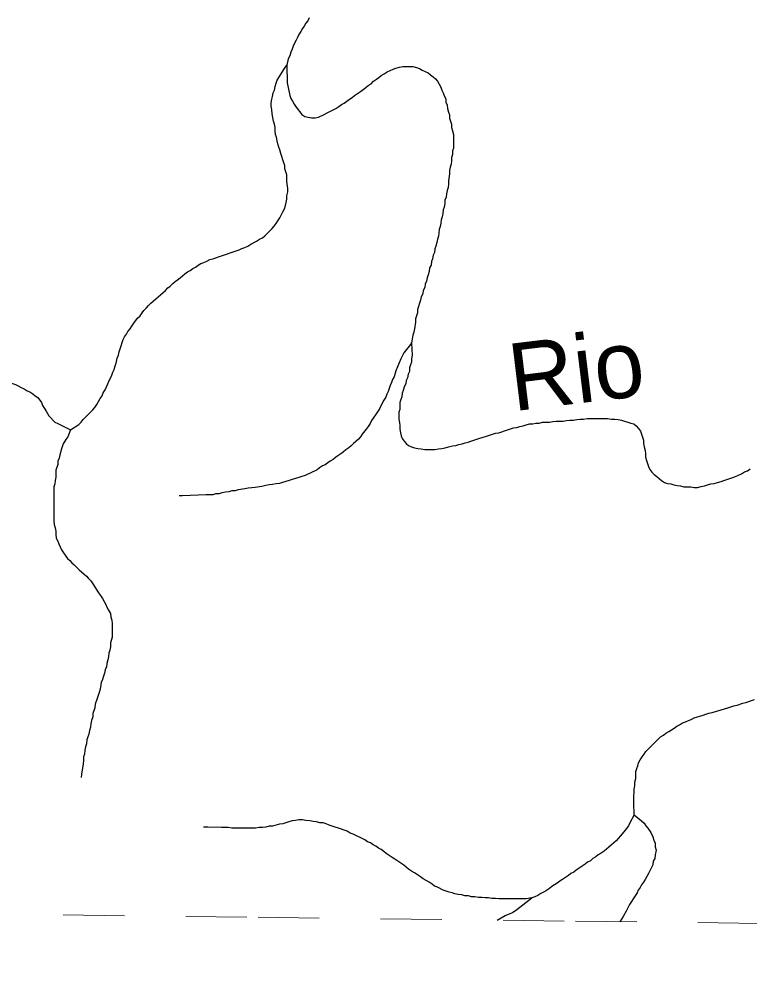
# Model space of a CAD drawing. Extents: x 652.3 to 678, y 7316.9 to 7344.9.
# Drawn here: x 670.031 to 671.224, y 7316.944 to 7318.499 of the extents above; entities that cross this region are included whole.
import ezdxf
from ezdxf.enums import TextEntityAlignment as Align

# ---------------------------------------------------------------- set-up
doc = ezdxf.new("R2010")
doc.units = 0
doc.header["$LTSCALE"] = 0.032
doc.linetypes.add('SHORT_DASHED', pattern=[2.7, 1.5, -1.2])
doc.layers.add('53', color=7, linetype='SHORT_DASHED', lineweight=13)
doc.layers.add('7', color=7, linetype='Continuous', lineweight=25)
doc.layers.add('61', color=7, linetype='Continuous')

msp = doc.modelspace()

# ---------------------------------------------------------------- linework, layer by layer
at = {"layer": '53'}
msp.add_lwpolyline([(666.2765, 7317.0825), (666.7945, 7317.0764), (667.3126, 7317.0703), (667.8307, 7317.0642), (668.3488, 7317.058), (668.8669, 7317.0519), (669.385, 7317.0457), (669.9031, 7317.0395), (670.4212, 7317.0333), (670.9393, 7317.027), (671.4574, 7317.0207), (671.9755, 7317.0145), (672.4936, 7317.0082), (673.0117, 7317.0018), (673.5298, 7316.9955), (674.0479, 7316.9891), (674.566, 7316.9828), (675.0841, 7316.9764), (675.6022, 7316.9699), (676.1203, 7316.9635), (676.6384, 7316.9571), (677.1565, 7316.9506), (677.6746, 7316.9441)], dxfattribs=at)
at = {"layer": '7'}
msp.add_line((670.4681, 7318.424), (670.4689, 7318.3954), dxfattribs=at)
for points in [[(670.5047, 7318.5012), (670.5023, 7318.4964), (670.4991, 7318.4925), (670.4967, 7318.4877), (670.4935, 7318.4837), (670.4911, 7318.4789), (670.488, 7318.4742), (670.4856, 7318.4694), (670.4832, 7318.4646), (670.4808, 7318.4598), (670.4784, 7318.4551), (670.4768, 7318.4503), (670.4744, 7318.4455), (670.4728, 7318.4392), (670.4704, 7318.4344), (670.4681, 7318.424)], [(670.4553, 7318.2904), (670.4537, 7318.2959), (670.4521, 7318.3007), (670.4514, 7318.3063), (670.4498, 7318.311), (670.449, 7318.3166), (670.449, 7318.3222), (670.4482, 7318.3278), (670.4466, 7318.3325), (670.4442, 7318.3445), (670.4434, 7318.3516), (670.4426, 7318.3572), (670.4426, 7318.3628), (670.4434, 7318.3683), (670.445, 7318.3731), (670.4458, 7318.3787), (670.4482, 7318.3835), (670.449, 7318.389), (670.4506, 7318.3946), (670.4521, 7318.3994), (670.4553, 7318.4041), (670.4641, 7318.4186), (670.4681, 7318.424)], [(670.4689, 7318.3954), (670.4728, 7318.3747), (670.4744, 7318.3699), (670.4776, 7318.3652), (670.48, 7318.3604), (670.4832, 7318.3556), (670.4927, 7318.3437), (670.4975, 7318.3405), (670.5031, 7318.3389), (670.5086, 7318.3381), (670.5142, 7318.3381), (670.5198, 7318.3389), (670.5293, 7318.3437), (670.5341, 7318.3461), (670.5484, 7318.3532), (670.5532, 7318.3564), (670.5572, 7318.3596), (670.562, 7318.362), (670.5659, 7318.3652), (670.5707, 7318.3683), (670.5747, 7318.3715), (670.5787, 7318.3747), (670.5834, 7318.3779), (670.5882, 7318.3811), (670.593, 7318.3843), (670.597, 7318.3874), (670.6009, 7318.3906), (670.6057, 7318.3938), (670.6097, 7318.3978), (670.6145, 7318.401), (670.6184, 7318.4041), (670.6224, 7318.4073), (670.6272, 7318.4097), (670.632, 7318.4129), (670.6415, 7318.4177), (670.6463, 7318.4193), (670.6519, 7318.4209), (670.6574, 7318.4216), (670.6741, 7318.4216), (670.6797, 7318.4201), (670.6845, 7318.4185), (670.6893, 7318.4161), (670.694, 7318.4137), (670.6988, 7318.4113), (670.7028, 7318.4081), (670.7068, 7318.4049), (670.7107, 7318.4018), (670.7139, 7318.3978), (670.7171, 7318.393), (670.7195, 7318.3882), (670.7211, 7318.3835), (670.7235, 7318.3787), (670.7251, 7318.3739), (670.7275, 7318.3691), (670.7275, 7318.3636), (670.7298, 7318.3588), (670.7306, 7318.3532), (670.7322, 7318.3476), (670.7338, 7318.3429), (670.7338, 7318.3373), (670.737, 7318.3278), (670.737, 7318.3222), (670.7386, 7318.3166), (670.7402, 7318.311), (670.7402, 7318.2888), (670.7386, 7318.284), (670.7386, 7318.2784), (670.737, 7318.2736), (670.737, 7318.2681), (670.7362, 7318.2625), (670.7346, 7318.2577), (670.7338, 7318.2522), (670.7338, 7318.2466), (670.7322, 7318.2355), (670.7322, 7318.2299), (670.7314, 7318.2243), (670.7298, 7318.2195), (670.729, 7318.214), (670.7283, 7318.2084), (670.7259, 7318.2036), (670.7259, 7318.1981), (670.7251, 7318.1925), (670.7235, 7318.1877), (670.7227, 7318.1821), (670.7219, 7318.1766), (670.7203, 7318.1718), (670.7195, 7318.1662), (670.7187, 7318.1607), (670.7171, 7318.1559), (670.7163, 7318.1503), (670.7155, 7318.1447), (670.7139, 7318.14), (670.7131, 7318.1344), (670.7115, 7318.1288), (670.71, 7318.1241), (670.7092, 7318.1185), (670.7068, 7318.1137), (670.706, 7318.1081), (670.7044, 7318.1034), (670.7036, 7318.0978), (670.7012, 7318.093)], [(670.1148, 7317.8289), (670.1283, 7317.8376), (670.1323, 7317.8416), (670.1355, 7317.8456), (670.1394, 7317.8495), (670.1434, 7317.8535), (670.1514, 7317.8615), (670.1546, 7317.8655), (670.1577, 7317.8702), (670.1609, 7317.875), (670.1633, 7317.8798), (670.1665, 7317.8846), (670.1681, 7317.8893), (670.1713, 7317.8941), (670.176, 7317.9037), (670.1776, 7317.9084), (670.18, 7317.9132), (670.1824, 7317.918), (670.184, 7317.9228), (670.1864, 7317.9275), (670.188, 7317.9331), (670.1896, 7317.9379), (670.1912, 7317.9458), (670.1935, 7317.9506), (670.1943, 7317.9562), (670.1975, 7317.9657), (670.1991, 7317.9713), (670.2007, 7317.9761), (670.2031, 7317.9808), (670.2063, 7317.9848), (670.2087, 7317.9896), (670.2126, 7317.9936), (670.215, 7317.9983), (670.2182, 7318.0031), (670.2246, 7318.0111), (670.2286, 7318.0151), (670.2317, 7318.0198), (670.2349, 7318.0238), (670.2389, 7318.0278), (670.2421, 7318.0318), (670.2461, 7318.0357), (670.25, 7318.0389), (670.254, 7318.0429), (670.258, 7318.0461), (670.262, 7318.0493), (670.266, 7318.0532), (670.2699, 7318.0564), (670.2739, 7318.0604), (670.2779, 7318.0636), (670.2819, 7318.0676), (670.2858, 7318.0707), (670.2898, 7318.0739), (670.2938, 7318.0771), (670.2978, 7318.0803), (670.3018, 7318.0835), (670.3057, 7318.0867), (670.3105, 7318.0891), (670.3145, 7318.0922), (670.3193, 7318.0946), (670.3232, 7318.0978), (670.328, 7318.1002), (670.3328, 7318.1018), (670.3376, 7318.1042), (670.3423, 7318.1066), (670.3471, 7318.1081), (670.3614, 7318.1129), (670.3662, 7318.1145), (670.3805, 7318.1193), (670.3853, 7318.1209), (670.3901, 7318.1225), (670.3949, 7318.1249), (670.3996, 7318.1264), (670.4044, 7318.1288), (670.4092, 7318.132), (670.4187, 7318.1368), (670.4235, 7318.14), (670.4283, 7318.1424), (670.4323, 7318.1455), (670.4442, 7318.1575), (670.4474, 7318.1615), (670.4506, 7318.1654), (670.4537, 7318.1702), (670.4569, 7318.175), (670.4617, 7318.1845), (670.4641, 7318.1893), (670.4657, 7318.1949), (670.4673, 7318.1997), (670.4681, 7318.2052), (670.4681, 7318.2108), (670.4697, 7318.2172), (670.4697, 7318.2227), (670.4681, 7318.2339), (670.4681, 7318.245), (670.4649, 7318.2546), (670.4649, 7318.2601), (670.4633, 7318.2649), (670.4617, 7318.2697), (670.4601, 7318.2752), (670.4585, 7318.28), (670.4569, 7318.2856), (670.4553, 7318.2904)], [(670.7012, 7318.093), (670.7004, 7318.0875), (670.6988, 7318.0819), (670.6972, 7318.0771), (670.6964, 7318.0715), (670.694, 7318.0668), (670.6932, 7318.0612), (670.6909, 7318.0564), (670.6901, 7318.0509), (670.6877, 7318.0461), (670.6861, 7318.0405), (670.6845, 7318.0357), (670.6829, 7318.0302), (670.6813, 7318.0254), (670.6813, 7318.0198), (670.6797, 7318.0151), (670.6781, 7318.0103), (670.6781, 7318.0047), (670.6765, 7317.9936), (670.6757, 7317.988), (670.6741, 7317.9832), (670.6718, 7317.9706)], [(670.6718, 7317.9706), (670.6698, 7317.9683), (670.659, 7317.9546), (670.6543, 7317.945), (670.6463, 7317.9251), (670.6431, 7317.9156), (670.6407, 7317.9108), (670.6391, 7317.906), (670.6367, 7317.9013), (670.6352, 7317.8965), (670.6336, 7317.8917), (670.6312, 7317.8869), (670.6296, 7317.8822), (670.6264, 7317.8774), (670.624, 7317.8726), (670.6192, 7317.8631), (670.6161, 7317.8583), (670.6129, 7317.8535), (670.6065, 7317.844), (670.6041, 7317.8392), (670.6009, 7317.8344), (670.5978, 7317.8297), (670.5914, 7317.8217), (670.5882, 7317.8177), (670.585, 7317.8137), (670.581, 7317.8098), (670.5771, 7317.8066), (670.5731, 7317.8026), (670.5691, 7317.7994), (670.5643, 7317.7962), (670.5604, 7317.7931), (670.5564, 7317.7899), (670.5516, 7317.7867), (670.5476, 7317.7835), (670.5437, 7317.7803), (670.5389, 7317.7779), (670.5349, 7317.7748), (670.5309, 7317.7716), (670.5261, 7317.77), (670.5214, 7317.7668), (670.5174, 7317.7636), (670.4983, 7317.7541), (670.4927, 7317.7525), (670.488, 7317.7509), (670.4824, 7317.7493), (670.4768, 7317.7477), (670.472, 7317.7461), (670.4609, 7317.7429), (670.4561, 7317.7413), (670.4506, 7317.7405), (670.445, 7317.7397), (670.4394, 7317.7389), (670.4338, 7317.7382), (670.4275, 7317.7366), (670.4163, 7317.735), (670.4108, 7317.7342), (670.4052, 7317.7334), (670.3996, 7317.7326), (670.3885, 7317.731), (670.3837, 7317.7294), (670.3781, 7317.7294), (670.3734, 7317.7278), (670.3678, 7317.727), (670.3622, 7317.7262), (670.3575, 7317.7246), (670.3519, 7317.7246), (670.3471, 7317.723), (670.336, 7317.723), (670.2978, 7317.7214), (670.2922, 7317.7212)], [(670.6718, 7317.9706), (670.6718, 7317.9705), (670.6726, 7317.9506), (670.6718, 7317.945), (670.6718, 7317.9395), (670.6702, 7317.9347), (670.6686, 7317.9299), (670.6686, 7317.9243), (670.6662, 7317.9196), (670.6654, 7317.914), (670.663, 7317.9092), (670.6622, 7317.9037), (670.6598, 7317.8989), (670.6582, 7317.8933), (670.6566, 7317.8885), (670.6558, 7317.883), (670.6543, 7317.8782), (670.6527, 7317.8734), (670.6527, 7317.8678), (670.6527, 7317.8623), (670.6511, 7317.8575), (670.6511, 7317.8519), (670.6511, 7317.8464), (670.6519, 7317.8408), (670.6527, 7317.8352), (670.6527, 7317.8297), (670.6535, 7317.8241), (670.655, 7317.8193), (670.6566, 7317.8145), (670.6598, 7317.8106), (670.663, 7317.8066), (670.667, 7317.8034), (670.6718, 7317.801), (670.6765, 7317.7994), (670.6821, 7317.7986), (670.6877, 7317.7978), (670.6932, 7317.797), (670.6988, 7317.797), (670.7044, 7317.797), (670.71, 7317.797), (670.7155, 7317.7978), (670.7211, 7317.7986), (670.7267, 7317.7994), (670.7322, 7317.801), (670.7386, 7317.8026), (670.7442, 7317.8034), (670.7489, 7317.805), (670.7545, 7317.8058), (670.7593, 7317.8074), (670.7641, 7317.809), (670.7688, 7317.8106), (670.7736, 7317.8122), (670.7784, 7317.8137), (670.7832, 7317.8153), (670.7887, 7317.8169), (670.7943, 7317.8185), (670.7991, 7317.8201), (670.8038, 7317.8217), (670.8086, 7317.8233), (670.8142, 7317.8241), (670.819, 7317.8257), (670.8237, 7317.8273), (670.8285, 7317.8289), (670.8333, 7317.8305), (670.8381, 7317.832), (670.8436, 7317.8328), (670.8484, 7317.8344), (670.854, 7317.8352), (670.8587, 7317.8368), (670.8643, 7317.8384), (670.8699, 7317.8384), (670.8747, 7317.84), (670.8802, 7317.84), (670.8858, 7317.8416), (670.8914, 7317.8416), (670.8969, 7317.8416), (670.9025, 7317.8424), (670.9081, 7317.8432), (670.9136, 7317.8432), (670.9192, 7317.8432), (670.9248, 7317.844)], [(670.0018, 7317.9116), (670.0105, 7317.9084), (670.0153, 7317.906), (670.0201, 7317.9045), (670.0249, 7317.9029), (670.0296, 7317.9005), (670.0344, 7317.8981), (670.0392, 7317.8957), (670.044, 7317.8925), (670.0487, 7317.8909), (670.0535, 7317.8877), (670.0575, 7317.8846), (670.0615, 7317.8814), (670.0678, 7317.8734), (670.0694, 7317.8686), (670.0726, 7317.8639), (670.075, 7317.8591), (670.0798, 7317.8519), (670.0893, 7317.8416), (670.0941, 7317.8392), (670.1148, 7317.8289)], [(670.9248, 7317.844), (670.9304, 7317.8448), (670.9359, 7317.8448), (670.9415, 7317.8456), (670.9471, 7317.8464), (670.9526, 7317.8464), (670.9582, 7317.8472), (670.9638, 7317.8472), (670.9693, 7317.8472), (670.9749, 7317.8472), (670.9805, 7317.8472), (670.9861, 7317.8472), (670.9916, 7317.8472), (670.998, 7317.8464), (671.0036, 7317.8464), (671.0091, 7317.8456), (671.0147, 7317.8448), (671.0195, 7317.8432), (671.025, 7317.8416), (671.0298, 7317.84), (671.0346, 7317.8384), (671.0386, 7317.8352), (671.0425, 7317.8312), (671.0457, 7317.8265), (671.0473, 7317.8217), (671.0489, 7317.8169), (671.0505, 7317.8122), (671.0505, 7317.8066), (671.0513, 7317.801), (671.0529, 7317.7954), (671.0537, 7317.7899), (671.0537, 7317.7843), (671.0553, 7317.7787), (671.0569, 7317.774), (671.0585, 7317.7692), (671.0608, 7317.7644), (671.064, 7317.7596), (671.068, 7317.7557), (671.072, 7317.7525), (671.076, 7317.7493), (671.0799, 7317.7461), (671.0847, 7317.7429), (671.0895, 7317.7413), (671.0951, 7317.7405), (671.0998, 7317.7389), (671.1054, 7317.7382), (671.111, 7317.7374), (671.1165, 7317.7358), (671.1221, 7317.7358), (671.1277, 7317.7358), (671.1333, 7317.735), (671.1388, 7317.735), (671.1444, 7317.7366), (671.15, 7317.7374), (671.1547, 7317.7389), (671.1603, 7317.7405), (671.1659, 7317.7413), (671.1714, 7317.7429), (671.177, 7317.7445), (671.1818, 7317.7461), (671.1866, 7317.7477), (671.1913, 7317.7493), (671.1961, 7317.7509), (671.2009, 7317.7525), (671.2057, 7317.7549), (671.2104, 7317.7572), (671.2152, 7317.7604), (671.22, 7317.762), (671.2248, 7317.7652)], [(670.1148, 7317.8289), (670.1108, 7317.8177), (670.1076, 7317.8129), (670.1028, 7317.8058), (670.1005, 7317.7978), (670.0973, 7317.7883), (670.0965, 7317.7827), (670.0941, 7317.7779), (670.0941, 7317.7724), (670.0909, 7317.7628), (670.0909, 7317.7517), (670.0901, 7317.7461), (670.0893, 7317.7405), (670.0877, 7317.7358), (670.0877, 7317.6801), (670.0885, 7317.6745), (670.0901, 7317.6689), (670.0909, 7317.6634), (670.0909, 7317.6578), (670.0917, 7317.6522), (670.0941, 7317.6474), (670.0957, 7317.6427), (670.1005, 7317.6331), (670.1036, 7317.6283), (670.11, 7317.6188), (670.114, 7317.6156), (670.1172, 7317.6116), (670.1211, 7317.6085), (670.1291, 7317.6005), (670.1331, 7317.5973), (670.1371, 7317.5933), (670.141, 7317.5902), (670.1442, 7317.5862), (670.1482, 7317.5822), (670.1514, 7317.5774), (670.1609, 7317.5631), (670.1641, 7317.5583), (670.1673, 7317.5536), (670.1697, 7317.5488), (670.1729, 7317.544), (670.1745, 7317.5392), (670.1768, 7317.5345), (670.18, 7317.5289), (670.1808, 7317.5233), (670.1824, 7317.5185), (670.1832, 7317.513), (670.1832, 7317.4907), (670.18, 7317.4811), (670.18, 7317.4748), (670.1792, 7317.4692), (670.1776, 7317.4644), (670.1768, 7317.4589), (670.176, 7317.4533), (670.1745, 7317.4477), (670.1737, 7317.4422), (670.1713, 7317.4374), (670.1705, 7317.4318), (670.1689, 7317.427), (670.1673, 7317.4215), (670.1649, 7317.4167), (670.1633, 7317.4056), (670.1617, 7317.4), (670.1601, 7317.3952), (670.1585, 7317.3904), (670.1554, 7317.3809), (670.1546, 7317.3753), (670.1514, 7317.3658), (670.1514, 7317.3602), (670.149, 7317.3546), (670.1482, 7317.3491), (670.1474, 7317.3435), (670.1458, 7317.3379), (670.145, 7317.3324), (670.1434, 7317.3276), (670.1418, 7317.3228), (670.141, 7317.3164), (670.1394, 7317.3117), (670.1386, 7317.3061), (670.1379, 7317.2997), (670.1363, 7317.295), (670.1363, 7317.2894), (670.1355, 7317.2838), (670.1331, 7317.2671), (670.1323, 7317.2616)], [(671.0354, 7317.2003), (671.0346, 7317.2202), (671.0346, 7317.2313), (671.0354, 7317.2369), (671.0354, 7317.2424), (671.0362, 7317.248), (671.0362, 7317.2536), (671.0378, 7317.2599), (671.0378, 7317.2711), (671.0394, 7317.2759), (671.041, 7317.2806), (671.0425, 7317.2854), (671.0449, 7317.2902), (671.0481, 7317.295), (671.0513, 7317.2997), (671.0545, 7317.3037), (671.0784, 7317.3276), (671.0831, 7317.3308), (671.0871, 7317.3339), (671.0919, 7317.3363), (671.0959, 7317.3395), (671.1006, 7317.3419), (671.1046, 7317.3451), (671.1094, 7317.3475), (671.1142, 7317.3507), (671.1189, 7317.3522), (671.1237, 7317.3546), (671.1285, 7317.3562), (671.1333, 7317.3586), (671.1476, 7317.3634), (671.1524, 7317.365), (671.1571, 7317.3666), (671.1627, 7317.3674), (671.177, 7317.3721), (671.1826, 7317.3737), (671.1882, 7317.3753), (671.1977, 7317.3785), (671.2033, 7317.3793), (671.2128, 7317.3825), (671.2176, 7317.3841), (671.2319, 7317.3888)], [(670.8683, 7317.065), (670.8587, 7317.0634), (670.8142, 7317.0634), (670.8086, 7317.0642), (670.803, 7317.0642), (670.7975, 7317.065), (670.7919, 7317.065), (670.7863, 7317.0658), (670.7808, 7317.0658), (670.7752, 7317.0666), (670.7696, 7317.0666), (670.7649, 7317.0682), (670.7585, 7317.0682), (670.7537, 7317.0698), (670.7481, 7317.0706), (670.7426, 7317.0714), (670.7378, 7317.073), (670.733, 7317.0745), (670.7235, 7317.0777), (670.7139, 7317.0825), (670.7092, 7317.0841), (670.7052, 7317.0873), (670.7004, 7317.0905), (670.6956, 7317.0936), (670.6909, 7317.096), (670.6861, 7317.0992), (670.6813, 7317.1024), (670.6765, 7317.1056), (670.6718, 7317.1088), (670.667, 7317.1119), (670.663, 7317.1151), (670.659, 7317.1183), (670.6543, 7317.1215), (670.6495, 7317.1247), (670.6447, 7317.1279), (670.6399, 7317.131), (670.6352, 7317.1342), (670.6304, 7317.1374), (670.6264, 7317.1406), (670.6224, 7317.1438), (670.6177, 7317.1462), (670.6137, 7317.1493), (670.6089, 7317.1517), (670.6049, 7317.1549), (670.6001, 7317.1565), (670.5954, 7317.1597), (670.5763, 7317.1692), (670.5715, 7317.1708), (670.5667, 7317.174), (670.5524, 7317.1788), (670.5468, 7317.1804), (670.5373, 7317.1836), (670.5325, 7317.1859), (670.5277, 7317.1875), (670.5222, 7317.1875), (670.5166, 7317.1891), (670.511, 7317.1899), (670.5055, 7317.1907), (670.4991, 7317.1915), (670.4935, 7317.1923), (670.488, 7317.1923), (670.4824, 7317.1915), (670.4768, 7317.1907), (670.4712, 7317.1891)], [(671.0354, 7317.2003), (671.0282, 7317.1875), (671.0258, 7317.1828), (671.0203, 7317.1756), (671.0131, 7317.1661), (671.0091, 7317.1621), (671.0059, 7317.1581), (671.002, 7317.1549), (670.998, 7317.1517), (670.994, 7317.1478), (670.99, 7317.1446), (670.9861, 7317.1414), (670.9813, 7317.1382), (670.9765, 7317.135), (670.9725, 7317.1318), (670.9678, 7317.1294), (670.9638, 7317.1255), (670.959, 7317.1231), (670.955, 7317.1199), (670.9502, 7317.1167), (670.9455, 7317.1135), (670.9407, 7317.1104), (670.9367, 7317.1072), (670.9319, 7317.1048), (670.928, 7317.1016), (670.9232, 7317.0984), (670.9184, 7317.0952), (670.9136, 7317.0921), (670.9097, 7317.0889), (670.9049, 7317.0865), (670.9009, 7317.0833), (670.8969, 7317.0801), (670.8922, 7317.0769), (670.8874, 7317.0745), (670.8826, 7317.0722), (670.8778, 7317.069), (670.8731, 7317.0666), (670.8683, 7317.065)], [(671.0354, 7317.2003), (671.0473, 7317.1907), (671.0513, 7317.1867), (671.0545, 7317.1828), (671.0577, 7317.1788), (671.0624, 7317.1716), (671.0656, 7317.1645), (671.0672, 7317.1589), (671.0696, 7317.1541), (671.0696, 7317.1485), (671.0712, 7317.143), (671.0696, 7317.135), (671.0688, 7317.1294), (671.0664, 7317.1247), (671.0656, 7317.1191), (671.0585, 7317.1048), (671.0561, 7317.1), (671.0529, 7317.0952), (671.0505, 7317.0905), (671.0473, 7317.0865), (671.0449, 7317.0817), (671.0418, 7317.0777), (671.0402, 7317.073), (671.037, 7317.0682), (671.0274, 7317.0539), (671.0219, 7317.0435), (671.017, 7317.0344), (671.012, 7317.0261)], [(670.4712, 7317.1891), (670.4665, 7317.1875), (670.4617, 7317.1859), (670.4561, 7317.1851), (670.445, 7317.182), (670.4394, 7317.182), (670.4338, 7317.1804), (670.4283, 7317.1796), (670.4227, 7317.1796), (670.4171, 7317.1788), (670.3781, 7317.1788), (670.3726, 7317.1796), (670.3614, 7317.1796), (670.3392, 7317.1804), (670.332, 7317.1806)], [(670.8114, 7317.0286), (670.8245, 7317.0364), (670.8317, 7317.0387), (670.8365, 7317.0411), (670.8436, 7317.0459), (670.8683, 7317.065)]]:
    msp.add_lwpolyline(points, dxfattribs=at)

# ---------------------------------------------------------------- texts
at = {"layer": '61'}
msp.add_text('Rio', height=0.11, rotation=6.948, dxfattribs=at).set_placement((670.9472, 7317.8724), align=Align.CENTER)

doc.saveas('drawing.dxf')
